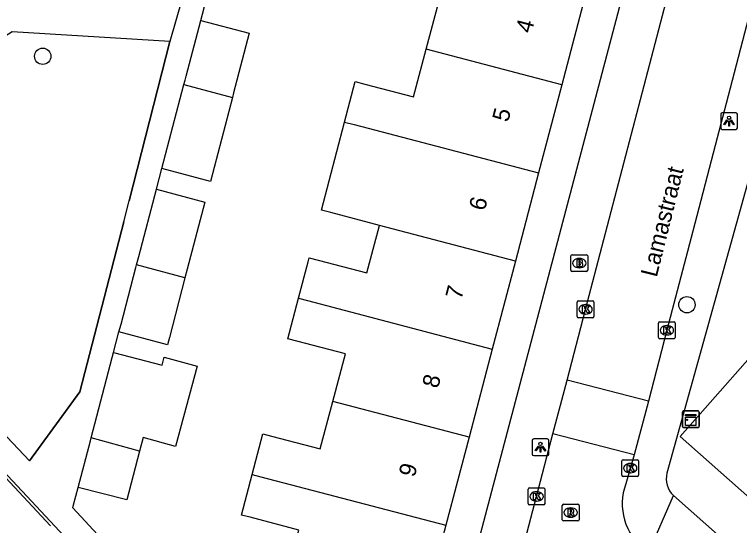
# Model space of a CAD drawing. Extents: x 163150 to 163546, y 380933 to 381635.
# Drawn here: x 163309.19 to 163352.42, y 381116.37 to 381146.82 of the extents above; entities that cross this region are included whole.
import ezdxf

# ---------------------------------------------------------------- set-up
doc = ezdxf.new("R2010")
doc.units = 0
for name, color, linetype in [('IMGEO_Boom', 7, 'Continuous'), ('IMGEO_Brandkraan', 7, 'Continuous'), ('IMGEO_Hek', 7, 'Continuous'), ('IMGEO_Kast', 7, 'Continuous'), ('IMGEO_Kolk', 7, 'Continuous'), ('IMGEO_Lichtpunt', 7, 'Continuous'), ('IMGEO_Openbare_ruimte_label', 7, 'Continuous'), ('IMGEO_Pand', 7, 'Continuous'), ('IMGEO_Pand_nummerreeks', 7, 'Continuous'), ('IMGEO_Parkeervlak_open', 7, 'Continuous'), ('IMGEO_Rijbaan_lokaal_open', 7, 'Continuous'), ('IMGEO_Rioolput', 7, 'Continuous'), ('IMGEO_Voetpad_open', 7, 'Continuous')]:
    doc.layers.add(name, color=color, linetype=linetype)

msp = doc.modelspace()

# ---------------------------------------------------------------- linework, layer by layer
at = {"layer": 'IMGEO_Boom'}
for centre in [(163310.871, 381144.332), (163349.284, 381129.527)]:
    msp.add_circle(centre, 0.489, dxfattribs=at)
at = {"layer": 'IMGEO_Brandkraan'}
for p, q in [((163342.364, 381131.581), (163342.364, 381132.433)), ((163342.439, 381132.507), (163343.291, 381132.507)), ((163342.852, 381132.287), (163342.877, 381132.287)), ((163343.365, 381132.433), (163343.365, 381131.581)), ((163343.291, 381131.507), (163342.439, 381131.507)), ((163342.875, 381131.727), (163342.85, 381131.727))]:
    msp.add_line(p, q, dxfattribs=at)
for points in [[(163342.364, 381131.581), (163342.364, 381132.433)], [(163342.439, 381132.507), (163343.291, 381132.507)], [(163343.365, 381132.433), (163343.365, 381131.581)], [(163342.712, 381132.207), (163342.712, 381131.807), (163342.925, 381131.807)], [(163342.943, 381132.207), (163342.712, 381132.207)], [(163342.891, 381132.126), (163342.837, 381132.126), (163342.837, 381132.05)], [(163342.837, 381132.05), (163342.89, 381132.05)], [(163342.899, 381131.974), (163342.837, 381131.974), (163342.837, 381131.893)], [(163342.837, 381131.893), (163342.899, 381131.893)], [(163343.291, 381131.507), (163342.439, 381131.507)]]:
    msp.add_lwpolyline(points, dxfattribs=at)
for centre, radius, start, end in [((163342.441, 381132.431), 0.0765, 91.552, 178.448), ((163342.441, 381132.431), 0.0765, 91.552, 178.448), ((163343.289, 381132.431), 0.0765, 1.552, 88.448), ((163343.289, 381132.431), 0.0765, 1.552, 88.448), ((163342.892, 381132.088), 0.0379, 267.8285, 90.9355), ((163342.9, 381131.933), 0.0404, 269.8759, 90.5077), ((163342.931, 381132.058), 0.251, 268.6676, 293.5347), ((163342.947, 381132.062), 0.145, 59.4692, 91.5367), ((163342.972, 381132.109), 0.0922, 285.5137, 58.1501), ((163342.977, 381131.917), 0.105, 301.3115, 78.989), ((163342.441, 381131.583), 0.0765, 181.552, 268.448), ((163342.441, 381131.583), 0.0765, 181.552, 268.448), ((163343.289, 381131.583), 0.0765, 271.552, 358.448), ((163343.289, 381131.583), 0.0765, 271.552, 358.448)]:
    msp.add_arc(centre, radius, start, end, dxfattribs=at)
for centre, major_axis, ratio, start_param, end_param in [((163342.851, 381132.007), (-0.387, 0.002), 0.722429, 4.712389, 7.853982), ((163342.876, 381132.007), (-0.39, 0.002), 0.717154, 1.570796, 4.712389)]:
    msp.add_ellipse(centre, major_axis=major_axis, ratio=ratio, start_param=start_param, end_param=end_param, dxfattribs=at)
at = {"layer": 'IMGEO_Hek'}
for points in [[(163318.448, 381145.215), (163309.044, 381145.786)], [(163318.448, 381145.215), (163316.034, 381135.723)], [(163315.715, 381134.476), (163316.034, 381135.723)], [(163315.715, 381134.476), (163313.079, 381124.337), (163310.086, 381120.226)], [(163310.086, 381120.226), (163298.375, 381132.601)]]:
    msp.add_lwpolyline(points, dxfattribs=at)
at = {"layer": 'IMGEO_Kast'}
for p, q in [((163349.085, 381123.204), (163349.926, 381123.204)), ((163349.926, 381123.204), (163349.085, 381123.204)), ((163349.01, 381122.279), (163349.01, 381123.12)), ((163349.01, 381123.12), (163349.01, 381122.279)), ((163350.01, 381123.129), (163350.01, 381122.288)), ((163350.01, 381122.288), (163350.01, 381123.129)), ((163349.935, 381122.204), (163349.094, 381122.204)), ((163349.094, 381122.204), (163349.935, 381122.204))]:
    msp.add_line(p, q, dxfattribs=at)
for points in [[(163349.205, 381122.994), (163349.805, 381122.994), (163349.805, 381122.909), (163349.205, 381122.909), (163349.205, 381122.994)], [(163349.205, 381122.819), (163349.805, 381122.819), (163349.805, 381122.33), (163349.205, 381122.33), (163349.205, 381122.819)]]:
    msp.add_lwpolyline(points, dxfattribs=at)
msp.add_circle((163349.289, 381122.668), 0.0377, dxfattribs=at)
for centre, start, end in [((163349.088, 381123.126), 92.4484, 184.2845), ((163349.088, 381123.126), 92.4484, 184.2845), ((163349.932, 381123.126), 2.4484, 94.2845), ((163349.932, 381123.126), 2.4484, 94.2845), ((163349.088, 381122.282), 182.4484, 274.2845), ((163349.088, 381122.282), 182.4484, 274.2845), ((163349.932, 381122.282), 272.4484, 4.2845), ((163349.932, 381122.282), 272.4484, 4.2845)]:
    msp.add_arc(centre, 0.0779, start, end, dxfattribs=at)
at = {"layer": 'IMGEO_Kolk'}
for p, q in [((163342.74, 381128.827), (163342.74, 381129.679)), ((163342.815, 381129.753), (163343.667, 381129.753)), ((163343.741, 381129.679), (163343.741, 381128.827)), ((163343.228, 381129.533), (163343.253, 381129.533)), ((163343.251, 381128.973), (163343.226, 381128.973)), ((163343.667, 381128.753), (163342.815, 381128.753)), ((163347.585, 381127.578), (163347.585, 381128.43)), ((163347.66, 381128.504), (163348.512, 381128.504)), ((163348.586, 381128.43), (163348.586, 381127.578)), ((163348.073, 381128.284), (163348.098, 381128.284)), ((163348.512, 381127.504), (163347.66, 381127.504)), ((163348.096, 381127.724), (163348.071, 381127.724)), ((163345.403, 381119.366), (163345.403, 381120.218)), ((163345.478, 381120.292), (163346.33, 381120.292)), ((163346.404, 381120.218), (163346.404, 381119.366)), ((163345.891, 381120.072), (163345.916, 381120.072)), ((163346.33, 381119.292), (163345.478, 381119.292)), ((163345.914, 381119.512), (163345.889, 381119.512)), ((163339.819, 381117.681), (163339.819, 381118.533)), ((163339.894, 381118.607), (163340.746, 381118.607)), ((163340.82, 381118.533), (163340.82, 381117.681)), ((163340.307, 381118.387), (163340.332, 381118.387)), ((163340.746, 381117.607), (163339.894, 381117.607)), ((163340.33, 381117.827), (163340.305, 381117.827))]:
    msp.add_line(p, q, dxfattribs=at)
for points in [[(163342.74, 381128.827), (163342.74, 381129.679)], [(163342.815, 381129.753), (163343.667, 381129.753)], [(163343.741, 381129.679), (163343.741, 381128.827)], [(163343.061, 381129.453), (163343.184, 381129.453), (163343.184, 381129.302), (163343.314, 381129.453), (163343.478, 381129.453), (163343.332, 381129.302), (163343.485, 381129.053), (163343.333, 381129.053), (163343.248, 381129.217), (163343.184, 381129.15), (163343.184, 381129.053), (163343.061, 381129.053), (163343.061, 381129.453)], [(163343.667, 381128.753), (163342.815, 381128.753)], [(163347.585, 381127.578), (163347.585, 381128.43)], [(163347.66, 381128.504), (163348.512, 381128.504)], [(163348.586, 381128.43), (163348.586, 381127.578)], [(163347.906, 381128.204), (163348.029, 381128.204), (163348.029, 381128.053), (163348.159, 381128.204), (163348.323, 381128.204), (163348.177, 381128.053), (163348.33, 381127.804), (163348.178, 381127.804), (163348.093, 381127.968), (163348.029, 381127.901), (163348.029, 381127.804), (163347.906, 381127.804), (163347.906, 381128.204)], [(163348.512, 381127.504), (163347.66, 381127.504)], [(163345.403, 381119.366), (163345.403, 381120.218)], [(163345.478, 381120.292), (163346.33, 381120.292)], [(163346.404, 381120.218), (163346.404, 381119.366)], [(163345.724, 381119.992), (163345.847, 381119.992), (163345.847, 381119.841), (163345.977, 381119.992), (163346.141, 381119.992), (163345.995, 381119.841), (163346.148, 381119.592), (163345.996, 381119.592), (163345.911, 381119.756), (163345.847, 381119.689), (163345.847, 381119.592), (163345.724, 381119.592), (163345.724, 381119.992)], [(163346.33, 381119.292), (163345.478, 381119.292)], [(163339.819, 381117.681), (163339.819, 381118.533)], [(163339.894, 381118.607), (163340.746, 381118.607)], [(163340.82, 381118.533), (163340.82, 381117.681)], [(163340.14, 381118.307), (163340.263, 381118.307), (163340.263, 381118.156), (163340.393, 381118.307), (163340.557, 381118.307), (163340.411, 381118.156), (163340.564, 381117.907), (163340.412, 381117.907), (163340.327, 381118.071), (163340.263, 381118.004), (163340.263, 381117.907), (163340.14, 381117.907), (163340.14, 381118.307)], [(163340.746, 381117.607), (163339.894, 381117.607)]]:
    msp.add_lwpolyline(points, dxfattribs=at)
for centre, start, end in [((163342.817, 381129.677), 91.552, 178.448), ((163342.817, 381129.677), 91.552, 178.448), ((163343.665, 381129.677), 1.552, 88.448), ((163343.665, 381129.677), 1.552, 88.448), ((163342.817, 381128.829), 181.552, 268.448), ((163342.817, 381128.829), 181.552, 268.448), ((163343.665, 381128.829), 271.552, 358.448), ((163343.665, 381128.829), 271.552, 358.448), ((163347.662, 381128.428), 91.552, 178.448), ((163347.662, 381128.428), 91.552, 178.448), ((163348.51, 381128.428), 1.552, 88.448), ((163348.51, 381128.428), 1.552, 88.448), ((163347.662, 381127.58), 181.552, 268.448), ((163347.662, 381127.58), 181.552, 268.448), ((163348.51, 381127.58), 271.552, 358.448), ((163348.51, 381127.58), 271.552, 358.448), ((163345.48, 381120.216), 91.552, 178.448), ((163345.48, 381120.216), 91.552, 178.448), ((163346.328, 381120.216), 1.552, 88.448), ((163346.328, 381120.216), 1.552, 88.448), ((163345.48, 381119.368), 181.552, 268.448), ((163345.48, 381119.368), 181.552, 268.448), ((163346.328, 381119.368), 271.552, 358.448), ((163346.328, 381119.368), 271.552, 358.448), ((163339.896, 381118.531), 91.552, 178.448), ((163339.896, 381118.531), 91.552, 178.448), ((163340.744, 381118.531), 1.552, 88.448), ((163340.744, 381118.531), 1.552, 88.448), ((163339.896, 381117.683), 181.552, 268.448), ((163339.896, 381117.683), 181.552, 268.448), ((163340.744, 381117.683), 271.552, 358.448), ((163340.744, 381117.683), 271.552, 358.448)]:
    msp.add_arc(centre, 0.0765, start, end, dxfattribs=at)
for centre, major_axis, ratio, start_param, end_param in [((163343.227, 381129.253), (-0.387, 0.002), 0.722429, 4.712389, 7.853982), ((163343.252, 381129.253), (-0.39, 0.002), 0.717154, 1.570796, 4.712389), ((163348.072, 381128.004), (-0.387, 0.002), 0.722429, 4.712389, 7.853982), ((163348.097, 381128.004), (-0.39, 0.002), 0.717154, 1.570796, 4.712389), ((163345.89, 381119.792), (-0.387, 0.002), 0.722429, 4.712389, 7.853982), ((163345.915, 381119.792), (-0.39, 0.002), 0.717154, 1.570796, 4.712389), ((163340.306, 381118.107), (-0.387, 0.002), 0.722429, 4.712389, 7.853982), ((163340.331, 381118.107), (-0.39, 0.002), 0.717154, 1.570796, 4.712389)]:
    msp.add_ellipse(centre, major_axis=major_axis, ratio=ratio, start_param=start_param, end_param=end_param, dxfattribs=at)
at = {"layer": 'IMGEO_Lichtpunt'}
for p, q in [((163352.2, 381140.968), (163351.392, 381140.968)), ((163352.2, 381140.968), (163351.392, 381140.968)), ((163351.298, 381140.873), (163351.298, 381140.066)), ((163351.298, 381140.873), (163351.298, 381140.066)), ((163352.294, 381140.066), (163352.294, 381140.873)), ((163352.294, 381140.066), (163352.294, 381140.873)), ((163351.392, 381139.972), (163352.2, 381139.972)), ((163351.392, 381139.972), (163352.2, 381139.972)), ((163340.051, 381121.438), (163340.051, 381120.631)), ((163340.051, 381121.438), (163340.051, 381120.631)), ((163340.953, 381121.533), (163340.145, 381121.533)), ((163340.953, 381121.533), (163340.145, 381121.533)), ((163341.047, 381120.631), (163341.047, 381121.438)), ((163341.047, 381120.631), (163341.047, 381121.438)), ((163340.145, 381120.537), (163340.953, 381120.537)), ((163340.145, 381120.537), (163340.953, 381120.537))]:
    msp.add_line(p, q, dxfattribs=at)
for points in [[(163351.672, 381140.537), (163351.711, 381140.509), (163351.523, 381140.247), (163351.485, 381140.274), (163351.672, 381140.537)], [(163351.774, 381140.489), (163351.821, 381140.489), (163351.821, 381140.167), (163351.774, 381140.167), (163351.774, 381140.489)], [(163351.884, 381140.509), (163351.922, 381140.536), (163352.109, 381140.274), (163352.07, 381140.246), (163351.884, 381140.509)], [(163340.425, 381121.102), (163340.464, 381121.074), (163340.276, 381120.812), (163340.238, 381120.839), (163340.425, 381121.102)], [(163340.527, 381121.054), (163340.574, 381121.054), (163340.574, 381120.732), (163340.527, 381120.732), (163340.527, 381121.054)], [(163340.637, 381121.074), (163340.675, 381121.101), (163340.862, 381120.839), (163340.823, 381120.811), (163340.637, 381121.074)]]:
    msp.add_lwpolyline(points, dxfattribs=at)
for centre in [(163351.797, 381140.671), (163340.55, 381121.236)]:
    msp.add_circle(centre, 0.0994, dxfattribs=at)
for centre, start, end in [((163351.392, 381140.873), 90, 180), ((163351.392, 381140.873), 90, 180), ((163352.2, 381140.873), 0, 90), ((163352.2, 381140.873), 0, 90), ((163351.392, 381140.066), 180, 270), ((163351.392, 381140.066), 180, 270), ((163352.2, 381140.066), 270, 0), ((163352.2, 381140.066), 270, 360), ((163340.145, 381121.438), 90, 180), ((163340.145, 381121.438), 90, 180), ((163340.953, 381121.438), 0, 90), ((163340.953, 381121.438), 0, 90), ((163340.145, 381120.631), 180, 270), ((163340.145, 381120.631), 180, 270), ((163340.953, 381120.631), 270, 0), ((163340.953, 381120.631), 270, 360)]:
    msp.add_arc(centre, 0.0946, start, end, dxfattribs=at)
at = {"layer": 'IMGEO_Pand'}
for points in [[(163333.739, 381144.749), (163334.49, 381147.578), (163331.588, 381148.339), (163330.992, 381148.495), (163331.626, 381150.913)], [(163343.205, 381147.878), (163341.822, 381142.63)], [(163319.295, 381142.658), (163319.36, 381142.906), (163319.422, 381143.142), (163320.294, 381146.461)], [(163320.294, 381146.461), (163323.186, 381145.701), (163322.252, 381142.148), (163322.183, 381141.885)], [(163328.872, 381140.413), (163329.507, 381142.831), (163330.086, 381142.679), (163332.988, 381141.919), (163333.739, 381144.749)], [(163341.822, 381142.63), (163333.739, 381144.749)], [(163317.978, 381137.645), (163319.295, 381142.658)], [(163319.295, 381142.658), (163322.183, 381141.885)], [(163341.822, 381142.63), (163340.439, 381137.382)], [(163322.183, 381141.885), (163320.866, 381136.872), (163317.978, 381137.645)], [(163330.955, 381134.256), (163328.055, 381135.025), (163327.498, 381135.171), (163328.872, 381140.413)], [(163328.872, 381140.413), (163329.445, 381140.263), (163340.439, 381137.382)], [(163340.439, 381137.382), (163339.056, 381132.133)], [(163316.468, 381131.895), (163316.602, 381132.407), (163317.656, 381136.42)], [(163317.656, 381136.42), (163320.544, 381135.647), (163319.493, 381131.649), (163319.355, 381131.123)], [(163326.119, 381129.912), (163326.69, 381132.092), (163326.753, 381132.33), (163327.301, 381132.186), (163330.203, 381131.426), (163330.955, 381134.256)], [(163339.056, 381132.133), (163330.955, 381134.256)], [(163315.42, 381127.905), (163315.54, 381128.362), (163316.431, 381131.755), (163316.468, 381131.895)], [(163319.355, 381131.123), (163316.468, 381131.895)], [(163339.056, 381132.133), (163337.673, 381126.883)], [(163319.355, 381131.123), (163318.424, 381127.583), (163318.306, 381127.133), (163315.42, 381127.905)], [(163361.33, 381126.6), (163363.22, 381128.774), (163362.727, 381129.202), (163361.089, 381130.626), (163356.961, 381125.957), (163354.549, 381128.09), (163348.873, 381121.67), (163353.033, 381117.992)], [(163328.17, 381123.764), (163328.921, 381126.593), (163326.019, 381127.354), (163325.485, 381127.494), (163326.119, 381129.912)], [(163326.119, 381129.912), (163326.66, 381129.77), (163337.673, 381126.883)], [(163313.761, 381121.59), (163315.018, 381126.375), (163315.101, 381126.69)], [(163315.101, 381126.69), (163317.987, 381125.918), (163318.114, 381126.4), (163320.079, 381125.869), (163318.786, 381121.084), (163316.854, 381121.606), (163316.645, 381120.811)], [(163337.673, 381126.883), (163336.29, 381121.636)], [(163323.365, 381119.412), (163323.999, 381121.83), (163324.517, 381121.694), (163327.419, 381120.933), (163328.17, 381123.764)], [(163336.29, 381121.636), (163328.17, 381123.764)], [(163312.983, 381118.631), (163313.717, 381121.422), (163313.761, 381121.59)], [(163316.645, 381120.811), (163313.761, 381121.59)], [(163336.29, 381121.636), (163334.907, 381116.386)], [(163316.645, 381120.811), (163315.879, 381117.898), (163312.983, 381118.631)], [(163334.907, 381116.386), (163333.459, 381110.892), (163328.625, 381112.166), (163325.323, 381113.036), (163326.136, 381116.101), (163323.234, 381116.861), (163322.731, 381116.993), (163323.365, 381119.412)], [(163323.365, 381119.412), (163323.876, 381119.278), (163334.907, 381116.386)], [(163308.652, 381119.232), (163311.339, 381116.359)]]:
    msp.add_lwpolyline(points, dxfattribs=at)
at = {"layer": 'IMGEO_Parkeervlak_open'}
msp.add_lwpolyline([(163318.448, 381145.215), (163309.044, 381145.786), (163307.687, 381144.941), (163304.985, 381145.89)], dxfattribs=at)
at = {"layer": 'IMGEO_Rijbaan_lokaal_open'}
for points in [[(163342.145, 381125.04), (163343.238, 381129.253), (163348.698, 381150.118), (163349.764, 381153.947)], [(163354.555, 381152.632), (163353.695, 381149.411), (163353.081, 381147.071), (163351.744, 381141.971), (163350.968, 381139.012), (163349.629, 381133.907), (163348.081, 381128.004), (163346.987, 381123.777)], [(163341.295, 381121.826), (163342.145, 381125.04)], [(163346.987, 381123.777), (163342.145, 381125.04)], [(163346.987, 381123.777), (163346.138, 381120.581)], [(163336.678, 381104.171), (163337.355, 381106.775), (163338.283, 381110.344), (163340.318, 381118.106), (163341.295, 381121.826)], [(163346.138, 381120.581), (163341.295, 381121.826)], [(163346.138, 381120.581), (163345.643, 381118.859)]]:
    msp.add_lwpolyline(points, dxfattribs=at)
msp.add_arc((163348.838, 381117.657), 3.413, 159.3859, 233.0931, dxfattribs=at)
at = {"layer": 'IMGEO_Rioolput'}
for p, q in [((163341.851, 381116.716), (163341.851, 381117.568)), ((163341.926, 381117.642), (163342.778, 381117.642)), ((163342.852, 381117.568), (163342.852, 381116.716)), ((163342.339, 381117.422), (163342.364, 381117.422)), ((163342.362, 381116.862), (163342.337, 381116.862)), ((163342.778, 381116.642), (163341.926, 381116.642))]:
    msp.add_line(p, q, dxfattribs=at)
for points in [[(163341.851, 381116.716), (163341.851, 381117.568)], [(163341.926, 381117.642), (163342.778, 381117.642)], [(163342.852, 381117.568), (163342.852, 381116.716)], [(163342.44, 381117.34), (163342.188, 381117.342), (163342.188, 381116.942)], [(163342.366, 381117.261), (163342.312, 381117.261), (163342.312, 381117.18)], [(163342.312, 381117.18), (163342.364, 381117.18)], [(163342.188, 381116.942), (163342.312, 381116.942), (163342.312, 381117.104), (163342.323, 381117.104)], [(163342.37, 381117.075), (163342.441, 381116.942), (163342.581, 381116.942), (163342.516, 381117.068)], [(163342.778, 381116.642), (163341.926, 381116.642)]]:
    msp.add_lwpolyline(points, dxfattribs=at)
for centre, radius, start, end in [((163341.928, 381117.566), 0.0765, 91.552, 178.448), ((163341.928, 381117.566), 0.0765, 91.552, 178.448), ((163342.776, 381117.566), 0.0765, 1.552, 88.448), ((163342.776, 381117.566), 0.0765, 1.552, 88.448), ((163342.348, 381117.369), 0.19, 274.7715, 282.9687), ((163342.372, 381117.165), 0.0964, 77.0061, 93.1865), ((163342.386, 381117.222), 0.0378, 276.6634, 79.6772), ((163342.439, 381117.23), 0.109, 350.3612, 89.416), ((163342.437, 381117.23), 0.112, 277.5842, 350.9817), ((163342.421, 381117.015), 0.108, 29.5134, 73.7905), ((163341.928, 381116.718), 0.0765, 181.552, 268.448), ((163341.928, 381116.718), 0.0765, 181.552, 268.448), ((163342.322, 381117.051), 0.0533, 26.0293, 88.6989), ((163342.776, 381116.718), 0.0765, 271.552, 358.448), ((163342.776, 381116.718), 0.0765, 271.552, 358.448)]:
    msp.add_arc(centre, radius, start, end, dxfattribs=at)
for centre, major_axis, ratio, start_param, end_param in [((163342.338, 381117.142), (-0.387, 0.002), 0.722429, 4.712389, 7.853982), ((163342.363, 381117.142), (-0.39, 0.002), 0.717154, 1.570796, 4.712389)]:
    msp.add_ellipse(centre, major_axis=major_axis, ratio=ratio, start_param=start_param, end_param=end_param, dxfattribs=at)
at = {"layer": 'IMGEO_Voetpad_open'}
for points in [[(163349.385, 381162.891), (163334.439, 381106.274), (163328.748, 381100.437), (163328.567, 381100.252)], [(163321.644, 381156.332), (163318.448, 381145.215)], [(163320.294, 381146.461), (163320.612, 381147.671), (163320.923, 381148.853)], [(163295.166, 381135.935), (163295.47, 381135.635), (163297.325, 381133.691), (163298.375, 381132.601), (163310.086, 381120.226), (163313.079, 381124.337), (163315.715, 381134.476), (163316.034, 381135.723), (163318.448, 381145.215)], [(163348.095, 381119.502), (163353.219, 381137.835), (163353.46, 381138.753)], [(163317.656, 381136.42), (163317.978, 381137.645)], [(163327.566, 381099.224), (163294.213, 381134.916)], [(163315.101, 381126.69), (163315.42, 381127.905)], [(163328.567, 381100.252), (163312.676, 381117.426), (163312.711, 381117.594), (163312.983, 381118.631)], [(163346.989, 381114.749), (163348.475, 381118.157)], [(163348.475, 381118.157), (163412.679, 381061.277)]]:
    msp.add_lwpolyline(points, dxfattribs=at)
msp.add_arc((163349.436, 381119.155), 1.386, 165.4865, 226.0664, dxfattribs=at)

# ---------------------------------------------------------------- texts
at = {"layer": 'IMGEO_Openbare_ruimte_label'}
msp.add_text('Lamastraat', height=1, rotation=75.936, dxfattribs=at).set_placement((163347.476, 381131.12))
at = {"layer": 'IMGEO_Pand_nummerreeks'}
for s, p in [('4', (163340.014, 381145.66)), ('5', (163338.62, 381140.369)), ('6', (163337.226, 381135.078)), ('7', (163335.831, 381129.787)), ('8', (163334.438, 381124.5)), ('9', (163333.043, 381119.205))]:
    msp.add_text(s, height=1, rotation=75.2408, dxfattribs=at).set_placement(p)

doc.saveas('drawing.dxf')
